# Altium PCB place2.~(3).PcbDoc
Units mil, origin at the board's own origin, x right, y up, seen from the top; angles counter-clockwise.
Board outline 2400 x 2000 mil, 2 copper layers (Top Layer, Bottom Layer), stack 62 mil thick; 51 components, 19 nets, 95 pads, 5 vias.
Unrouted connection lines stored in the file: 2.
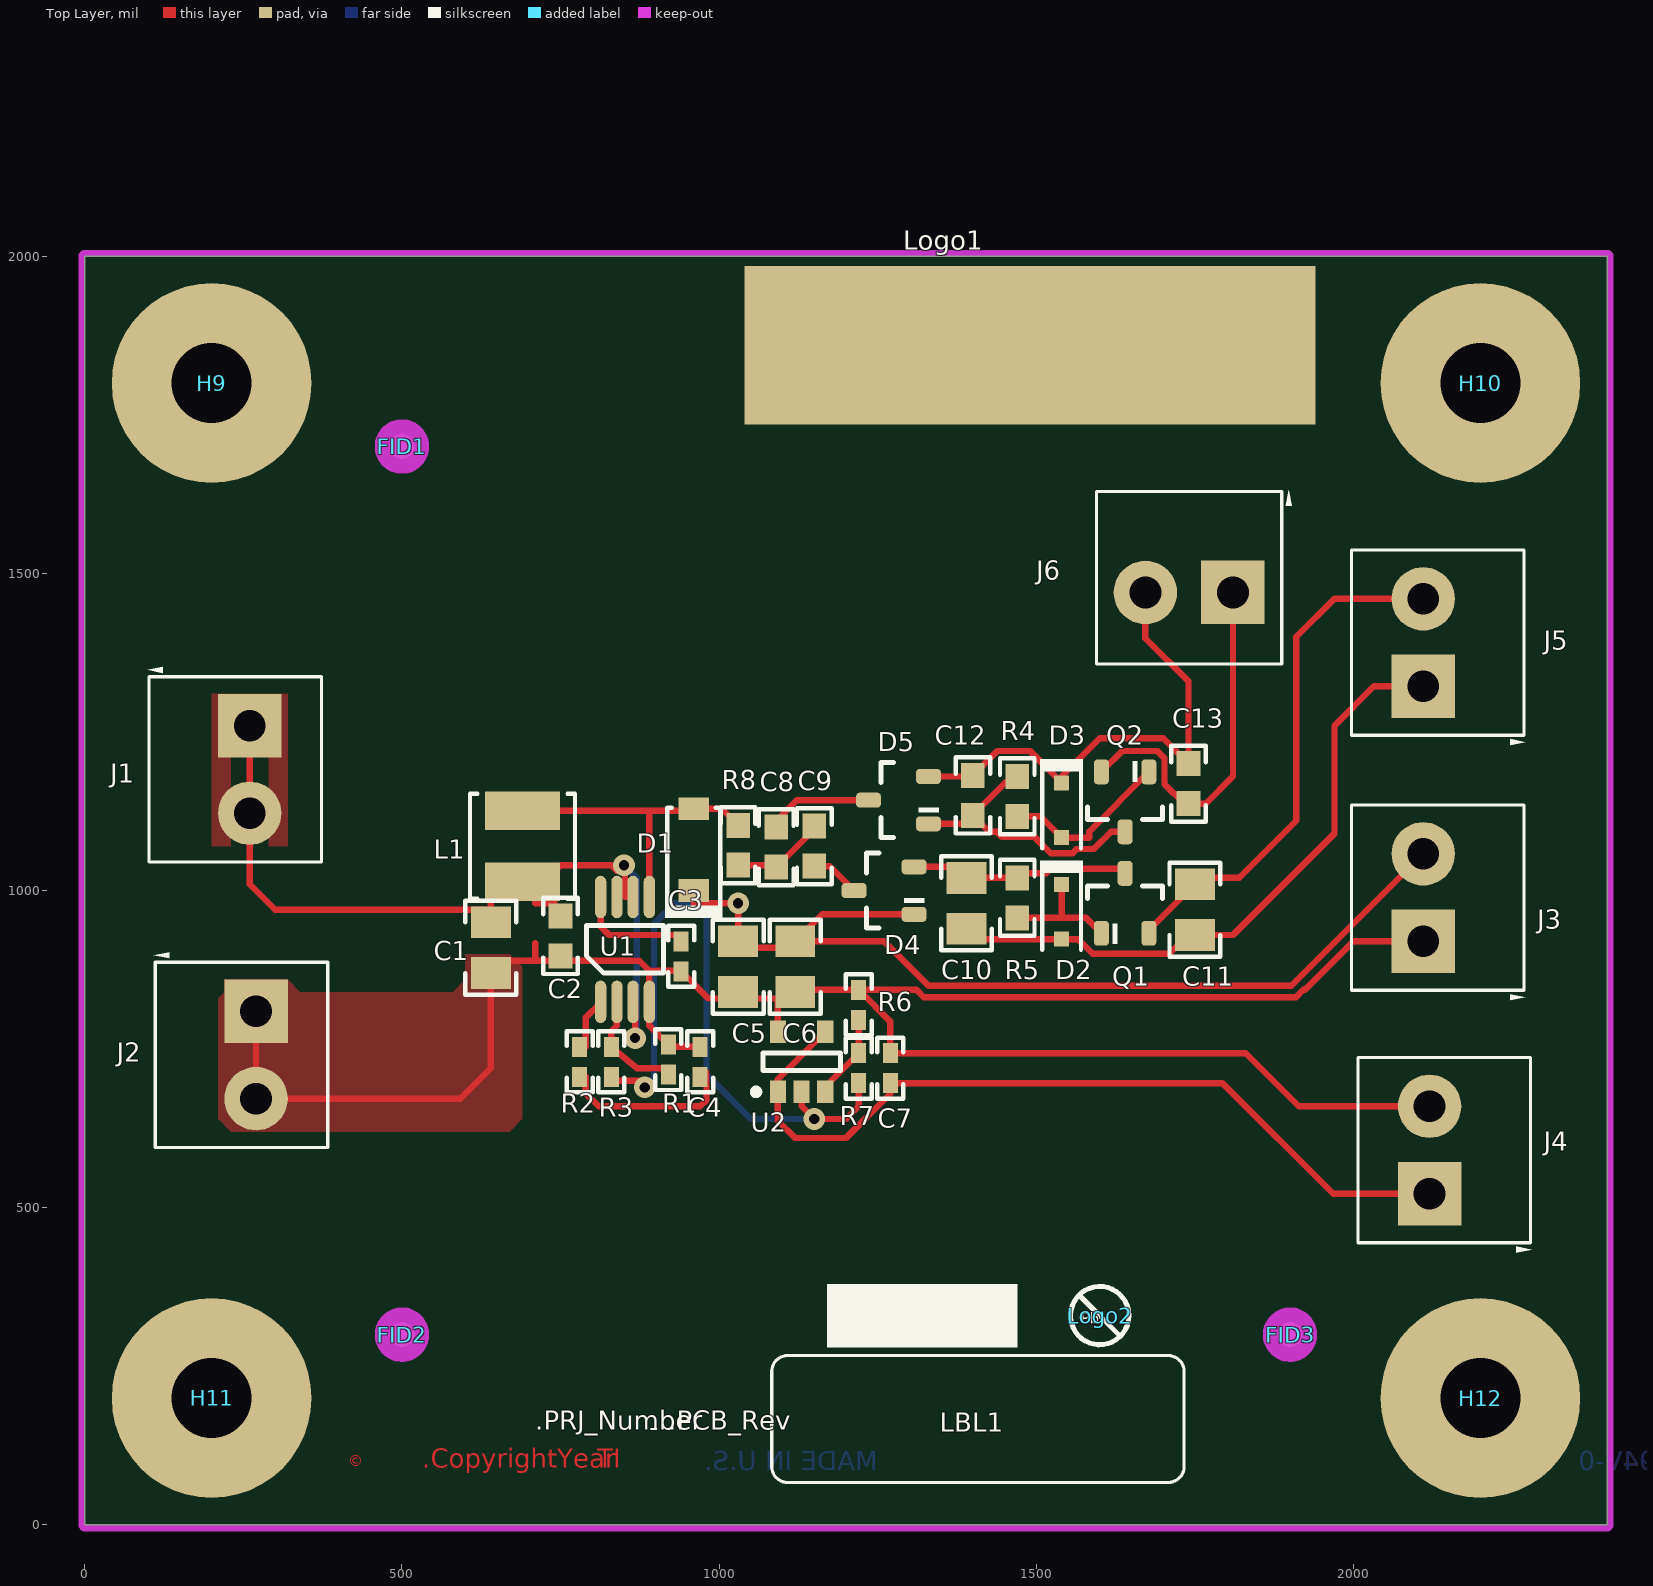
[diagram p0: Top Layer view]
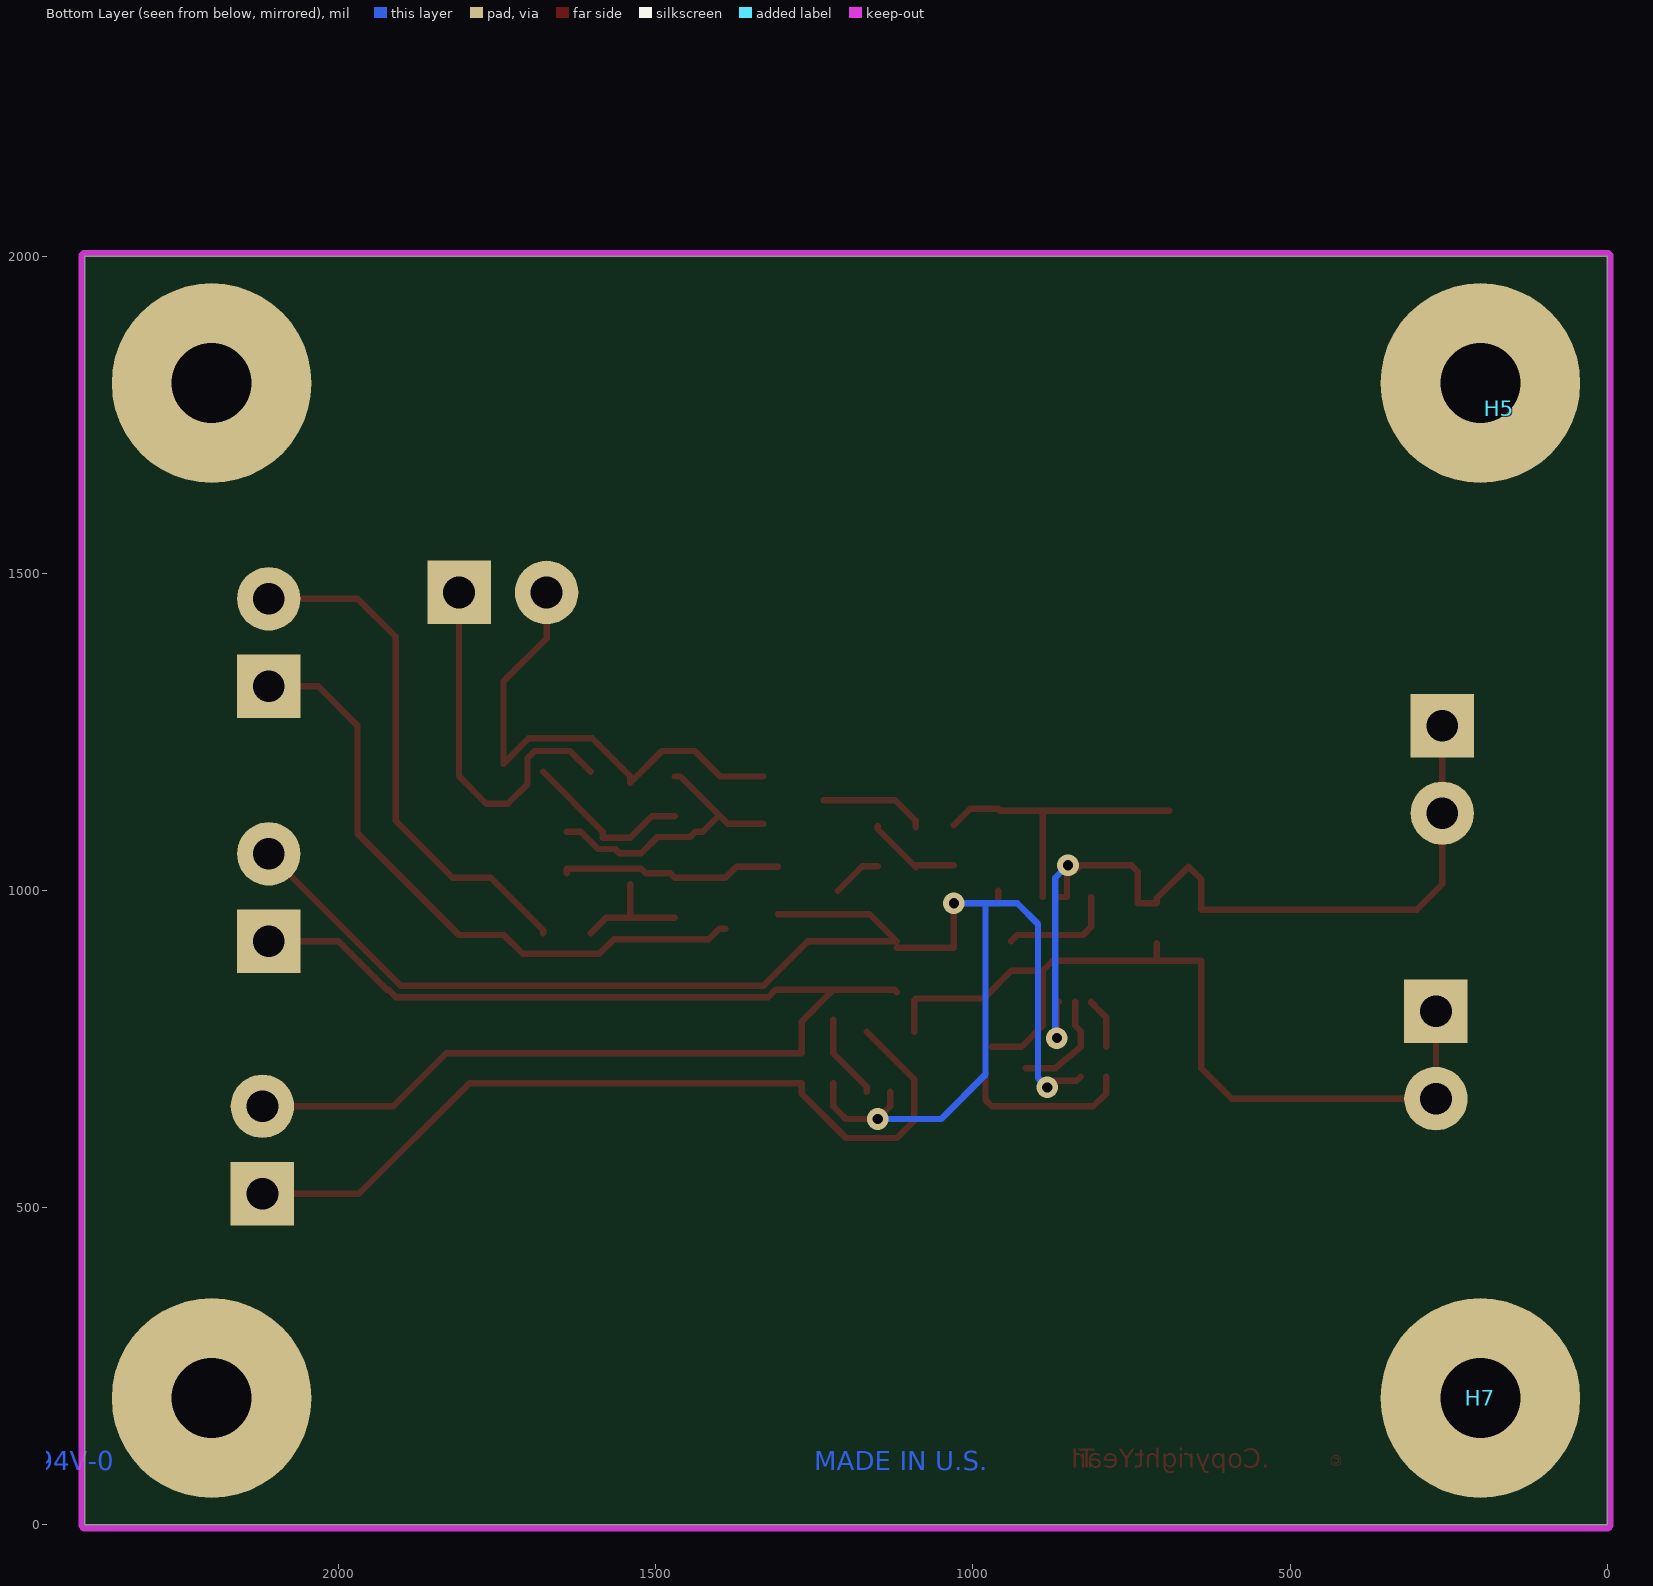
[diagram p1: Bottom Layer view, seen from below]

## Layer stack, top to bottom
Top Solder: solder mask 0.4, Solder Resist, Dk 3.5
Top Layer: signal copper 1.4
Dielectric1: core 59.2, FR-4, Dk 4.8
Bottom Layer: signal copper 1.4
Bottom Solder: solder mask 0.4, Solder Resist, Dk 3.5

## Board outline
0,0 2400,0 2400,2000 0,2000

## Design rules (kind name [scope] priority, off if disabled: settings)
AcuteAngle [All] p1: minimum=4.50000000000000E+0001 checktracksonly=FALSE
AssemblyTestPointUsage [All] p1: valid=2
Clearance Clearance_Keepouts [((IsTrack Or IsArc) And Not InPoly) And IsFree and IsKeepOut vs ((IsTrack Or IsArc) And Not InPoly) And IsFree and IsKeepOut] p1: gap=8
Clearance Clearance_BoardEdge_MountingHoles [OnCopper and InComponentClass('Mounting Holes') vs IsKeepOut] p2: gap=40
Clearance Clearance_BoardEdge_Poly [OnCopper and InPoly vs IsKeepOut] p3: gap=25
Clearance Clearance_BoardEdge [OnCopper and Not InComponentClass('Logo') and not InComponentClass('FiducialMark') and not InRegion(1000,500,4000,800) and Not IsKeepout vs IsKeepOut] p4: gap=75
Clearance Clearance_Poly [InPolygon] p5: gap=25
Clearance [All] p6: gap=7.87
ComponentClearance ComponentClearance_MountingHoles_FiducialMarks [InComponentClass('Mounting Holes') vs InComponentClass('FiducialMark')] p1: gap=10 collisioncheckmode=3 verticalgap=10 showdistances=FALSE
ComponentClearance ComponentClearance_Shunt [InComponentClass('Header') vs InComponentClass('Shunt')] p2: gap=0 collisioncheckmode=3 verticalgap=0 showdistances=FALSE
ComponentClearance ComponentClearance_Logo [InComponentClass('Logo')] p3: gap=10 collisioncheckmode=3 verticalgap=10 showdistances=FALSE
ComponentClearance ComponentClearance_ScrewToNut [(HasFootprint('NY PMS 440 0025 PH')) vs (HasFootprint('Keystone_1902C'))] p4: gap=5 collisioncheckmode=3 verticalgap=10 showdistances=FALSE
ComponentClearance ComponentClearance_MountingHoles [InComponentClass('Mounting Holes')] p5: gap=250 collisioncheckmode=3 verticalgap=100000 showdistances=FALSE
ComponentClearance ComponentClearance_SmallPassives [HasFootprint('0201*') or HasFootprint('0402*') or HasFootprint('0508') or HasFootprint('0603*') or HasFootprint('0612') or HasFootprint('0805*') or HasFootprint('0815*') or HasFootprint('0830*') or HasFootprint('1206*') or HasFootprint('1210*') or HasFootprint('1808*') or HasFootprint('1812*') or HasFootprint('1825*') or HasFootprint('2010*') or HasFootprint('2220*') or HasFootprint('2225*') or HasFootprint('2512*') or HasFootprint('2728*') or HasFootprint('3518*') vs HasFootprint('0201*') or HasFootprint('0402*') or HasFootprint('0508') or HasFootprint('0603*') or HasFootprint('0612') or HasFootprint('0805*') or HasFootprint('0815*') or HasFootprint('0830*') or HasFootprint('1206*') or HasFootprint('1210*') or HasFootprint('1808*') or HasFootprint('1812*') or HasFootprint('1825*') or HasFootprint('2010*') or HasFootprint('2220*') or HasFootprint('2225*') or HasFootprint('2512*') or HasFootprint('2728*') or HasFootprint('3518*')] p6: gap=20 collisioncheckmode=3 verticalgap=10 showdistances=FALSE
ComponentClearance ComponentClearance_THtoSMT [IsThruComponent vs IsSMTComponent] p7: gap=100 collisioncheckmode=3 verticalgap=30 showdistances=FALSE
ComponentClearance ComponentClearance_THtoTH [IsThruComponent vs IsThruComponent] p8: gap=118.11 collisioncheckmode=3 verticalgap=30 showdistances=FALSE
ComponentClearance [All] p9: gap=10 collisioncheckmode=3 verticalgap=10 showdistances=FALSE
DiffPairsRouting [All] p1: maxlimit=100 minlimit=10 mostfreqgap=10 toplayer_minwidth=15 toplayer_maxwidth=15 toplayer_prefwidth=15 bottomlayer_minwidth=15 bottomlayer_maxwidth=15 bottomlayer_prefwidth=15 maxuncoupledlength=1000
FabricationTestPointUsage TestPointUsage [All] p1: valid=2 allowmultiple=FALSE
FabricationTestpoint Testpoint [All] p1: side=3 testpointundercomponent=TRUE minsize=40 maxsize=100 preferedsize=60 minholesize=0 maxholesize=40 preferedholesize=32 testpointgrid=1 allowsidetop=TRUE allowsidebottom=TRUE usegrid=TRUE gridtolerance=0.01
FanoutControl Fanout_LCC [IsLCC] p1: bgadir=Out bgaviamode=Centered fanoutstyle=Auto fanoutdirection=Alternating viagrid=1 // Fanout_LCC (Default Rule)
FanoutControl Fanout_BGA [IsBGA] p2: bgadir=Out bgaviamode=Centered fanoutstyle=Auto fanoutdirection=Alternating viagrid=1 // Fanout_BGA (Default Rule)
FanoutControl Fanout_Default [All] p4: bgadir=Out bgaviamode=Centered fanoutstyle=Auto fanoutdirection=Alternating viagrid=1 // Fanout_Default (Default Rule)
FanoutControl Fanout_Small [(CompPinCount < 5)] p5: bgadir=Out bgaviamode=Centered fanoutstyle=Auto fanoutdirection=OutThenIn viagrid=1 // Fanout_Small (Default Rule)
HoleSize [All] p1: absolutevalues=TRUE maxlimit=251 minlimit=8 maxpercent=80.000 minpercent=20.000
MinimumAnnularRing MinimumAnnularRing_ThermalPadVias [IsVia and InAnyComponent] p1: minimumring=5.91
MinimumAnnularRing [All] p2: minimumring=9
MinimumSolderMaskSliver MinimumSolderMaskSliver_Logo [InComponentClass('Logo') vs InComponentClass('Logo')] p1: minsoldermaskwidth=0.7
MinimumSolderMaskSliver [All] p2: minsoldermaskwidth=3.94
PlaneConnect [All] p1: planeconnectstyle=Relief reliefexpansion=10 reliefentries=4 reliefconductorwidth=10 reliefairgap=10
PolygonConnect PolygonConnect_3 [All vs IsNamedPolygon('Top Layer-No Net 2')] p1: connectstyle=Direct reliefconductorwidth=10 reliefentries=4 polygonreliefangle="90 Angle" airgapwidth=10
PolygonConnect PolygonConnect_2 [All vs IsNamedPolygon('Top Layer-No Net 2')] p2: connectstyle=Direct reliefconductorwidth=10 reliefentries=4 polygonreliefangle="90 Angle" airgapwidth=10
PolygonConnect PolygonConnect_1 [All vs IsNamedPolygon('Top Layer-No Net 2')] p3: connectstyle=Direct reliefconductorwidth=10 reliefentries=4 polygonreliefangle="90 Angle" airgapwidth=10
PolygonConnect [All] p4: connectstyle=Direct reliefconductorwidth=10 reliefentries=4 polygonreliefangle="90 Angle" airgapwidth=10
RoutingVias ThermalPadVias [IsVia and InAnyComponent] p1: holewidth=7.87 width=19.68 viastyle="Through Hole" minholewidth=7.87 minwidth=19.68 maxholewidth=12.99 maxwidth=23.62
RoutingVias [All] p2: holewidth=16 width=34 viastyle="Through Hole" minholewidth=7.87 minwidth=26 maxholewidth=40 maxwidth=65
SilkToBoardRegionClearance [Not ((IsComment or IsDesignator) And (Hide <> 'False')) and not InRegion(1000,500,4000,800)] p1:
SilkToSilkClearance SilkToSilkClearance_Pb-FreeLogo [(HasFootprint('Pb-Free_Overlay_Medium') OR HasFootprint('Pb-Free_Overlay_Small')) vs (HasFootprint('Pb-Free_Overlay_Medium') OR HasFootprint('Pb-Free_Overlay_Small'))] p1: silktosilkclearance=0
SilkToSilkClearance [All] p2: silktosilkclearance=5
SilkToSolderMaskClearance "Silk to Solder Mask Opening" [All] p1: minsilkscreentomaskgap=1 clearancetoexposedcopper=FALSE
SolderMaskExpansion [All] p1: expansion=1.97
UnpouredPolygon [All] p1: allowunpoured=FALSE
Width [All] p1: maxlimit=100 minlimit=6 preferedwidth=10 checkconnectedcopper=TRUE
14 further rules are at their usual default settings.

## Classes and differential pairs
component class "TPS61085 reference board": C1 C2 C3 C4 C5 C6 C7 C8 C9 C10 C11 C12 C13 D1 D2 D3 D4 D5 J1 J2 J3 J4 J5 J6 L1 Q1 Q2 R1 R2 R3 R4 R5 R6 R7 R8 U1 U2
component class "Mounting Holes": H9 H10 H11 H12
component class Logo: Logo1
component class "TPS61085 reference board_Hardware": FID1 FID2 FID3 H5 H6 H7 H8 H9 H10 H11 H12 LBL1 Logo1 Logo2
component class FiducialMark: FID1 FID2 FID3
component class Label: LBL1

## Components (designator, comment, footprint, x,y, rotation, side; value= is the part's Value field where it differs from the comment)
C1 "GRM219R61A106KE44D" 0805_HV 640,910 r270 top
C2 "GRM185R61C105KE44D" 0603 750,928.5 r270 top
C3 "GRM155R71C104KA88D" 0402 940,896.38 r270 top
C4 "GRM155R61C222KA01D" 0402 970,730 r90 top
C5 "C2012X5R1E106K125AB" 0805_HV 1030,880 r270 top
C6 "C2012X5R1E106K125AB" 0805_HV 1120,880 r270 top
C7 "GRM155R71C104KA88D" 0402 1270,720 r90 top
C8 "06035C104KAT2A" 0603 1090,1068.5 r90 top
C9 "06035C104KAT2A" 0603 1150,1070 r90 top
C10 "C2012X7R1H105K125AB" 0805_HV 1390,980 r270 top
C11 "C2012X7R1H105K125AB" 0805_HV 1750,970 r270 top
C12 "GRM185R61C105KE44D" 0603 1400,1150 r90 top
C13 "GRM185R61C105KE44D" 0603 1740,1168.5 r90 top
D1 "MBR120LSFT1G" SOD-123FL 960,1064.47 r90 top
D2 "MMSZ5248BS-7-F" sod-323 1540,966.69 r270 top
D3 "MMSZ5236BS-7-F" sod-323 1540,1126.69 r270 top
D4 "BAT54SLT1G" SOT-23 1260,1000 r180 top
D5 "BAT54SLT1G" SOT-23 1282.76,1142.6 r180 top
FID1 "Fiducial" Fiducial10-20 500,1700 r0 top
FID2 "Fiducial" Fiducial10-20 500,300 r0 top
FID3 "Fiducial" Fiducial10-20 1900,300 r0 top
H5 "1902C" Keystone_1902C 170,1760 r180 bottom locked
H6 "1902C" Keystone_1902C 4750,3250 r180 bottom locked
H7 "1902C" Keystone_1902C 200,200 r180 bottom locked
H8 "1902C" Keystone_1902C 4050,200 r180 bottom locked
H9 "NY PMS 440 0025 PH" "NY PMS 440 0025 PH"#1 170,1760 r0 top
H10 "NY PMS 440 0025 PH" "NY PMS 440 0025 PH"#2 2900,2200 r0 top
H11 "NY PMS 440 0025 PH" "NY PMS 440 0025 PH"#3 200,200 r0 top locked
H12 "NY PMS 440 0025 PH" "NY PMS 440 0025 PH"#4 4050,200 r0 top
J1 "ED555/2DS" TERM_BLK_ED555-2DS 260,1260 r270 top
J2 "ED555/2DS" TERM_BLK_ED555-2DS 270,810 r270 top
J3 "ED555/2DS" TERM_BLK_ED555-2DS 2110,920 r90 top
J4 "ED555/2DS" TERM_BLK_ED555-2DS 2120,522 r90 top
J5 "ED555/2DS" TERM_BLK_ED555-2DS 2110,1322 r90 top
J6 "ED555/2DS" TERM_BLK_ED555-2DS 1810,1470 r180 top
L1 "LQH44PN3R3MP0L" IND_LQH44P 690,1070 r90 top
LBL1 "Size: 0.65\" x 0.20 \"" Label_650x200 1408,167 r0 top
Logo1 "Texas Instruments" TI_Stacked_SolderMask_Small 1490,1860 r180 top
Logo2 "Pb-Free Symbol" Pb-Free_Overlay_Small 1600,330 r0 top
Q1 "BC850CLT1G" SOT-23 1640,980 r90 top
Q2 "BC857C-7-F" SOT-23 1640,1140 r270 top
R1 "CRCW040216K0JNED" 0402 920,733.62 r270 top
R2 "CRCW040227K0JNED" 0402 780,730 r90 top
R3 "CRCW0402113KFKED" 0402 830,730 r270 top
R4 "CPF0603B2K0E" 0603 1470,1148.5 r90 top
R5 "CPF0603B2K0E" 0603 1470,988.5 r90 top
R6 "CRCW040227K0JNED" 0402 1220,820 r270 top
R7 "CRCW040227K0JNED" 0402 1220,720 r270 top
R8 "CRCW060310R0FKEA" 0603 1030,1071.5 r270 top
U1 "TPS61085DGKR" DGK0008A_N 851.61,907.32 r90 top
U2 "LM7321MF" MF05A_L 1130,730 r90 top

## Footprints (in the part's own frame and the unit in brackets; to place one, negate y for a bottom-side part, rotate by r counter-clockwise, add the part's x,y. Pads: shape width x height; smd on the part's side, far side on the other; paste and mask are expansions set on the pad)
0402 [mm] "0402 from SM-752 data"
  rect 0.8x0.6 smd: 1(-0.6,0) 2(0.6,0)
  silkscreen extent -1.22,-0.52 1.22,0.52, body extent -0.55,-0.3 0.55,0.3, height 0.6
0603 [mm] "0603 from SM-752 data"
  rect 1x0.95 smd: 1(-0.8,0) 2(0.8,0)
  silkscreen extent -1.52,-0.69 1.52,0.69, body extent -0.87,-0.47 0.87,0.47, height 0.85
0805_HV [mil] "0805 with 30mil clearance between pads"
  rect 50x63 smd: 1(-40,0) 2(40,0)
  silkscreen extent -74,-40 74,40, body extent -43,-29 43,29, height 43
DGK0008A_N [mm] "TSOP, 8-Leads, Body 3x3mm, Pitch 0.65mm, IPC Medium Density"
  oval 1.7x0.45 smd mask+0.05: 1(-2.1,0.975) 2(-2.1,0.325) 3(-2.1,-0.325) 4(-2.1,-0.975) 5(2.1,-0.975) 6(2.1,-0.325) 7(2.1,0.325) 8(2.1,0.975)
  silkscreen extent -0.95,-1.55 0.95,1.55, body extent -2.45,-1.5 2.45,1.5, height 0.94
Fiducial10-20 [mm]
  round 1 smd mask+0.5: 1(0,0)
  Top Layer keep-out circle w1.178: c0,0 r0.5
IND_LQH44P [mm] "Murata"
  rect 1.55x3 smd: 1(-1.425,0) 2(1.425,0)
  silkscreen extent -2.1,-2.1 2.1,2.1, body extent -2.1,-2.1 2.1,2.1, height 1.8
Keystone_1902C [mil] "Hex Standoff, 4-40 threaded, nylon"
  body extent -145,-126 146,126, height 501
Label_650x200 [mil] "Thermal Transfer Label"
  silkscreen extent -325,-100 325,100, body extent -326,-101 326,101, height 1
MF05A_L [mm] "SOT23, 5-Leads, Body 2.9x1.6mm, Pitch 0.95mm, Lead Span 2.8mm, IPC High Density"
  rect 0.9x0.65 smd: 1(-1.2,0.95) 2(-1.2,0) 3(-1.2,-0.95) 4(1.2,-0.95) 5(1.2,0.95)
  silkscreen extent -1.32,-1.55 0.35,1.95, body extent -0.9,-1.55 0.9,1.55, height 1.19
"NY PMS 440 0025 PH"#1 [mm] "4-40 nylon screw and mounting hole"
  round 8 hole 3.2: 1(0.762,1.016)
  body extent -3.3,-3.3 3.3,3.3, height 2.69
"NY PMS 440 0025 PH"#2 [mm] "4-40 nylon screw and mounting hole"
  round 8 hole 3.2: 1(-17.78,-10.16)
  body extent -3.3,-3.3 3.3,3.3, height 2.69
"NY PMS 440 0025 PH"#3 [mm] "4-40 nylon screw and mounting hole"
  round 8 hole 3.2: 1(0,0)
  body extent -3.3,-3.3 3.3,3.3, height 2.69
"NY PMS 440 0025 PH"#4 [mm] "4-40 nylon screw and mounting hole"
  round 8 hole 3.2: 1(-46.99,0)
  body extent -3.3,-3.3 3.3,3.3, height 2.69
Pb-Free_Overlay_Small [mil]
  silkscreen extent -46,-46 46,46
SOD-123FL [mm] "Copied from SOD-123"
  rect 0.915x1.22 smd: 1(-1.637,0) 2(1.637,0)
  silkscreen extent -2.74,-1.16 1.68,1.16, body extent -1.9,-0.9 1.9,0.9, height 1
sod-323 [mm] "NXP recommended land pattern"
  rect 0.6x0.6 smd paste-0.05: 1(-1.1,0) 2(1.1,0)
  silkscreen extent -2.06,-0.86 1.53,0.86, body extent -1.3,-0.67 1.3,0.68, height 1.1
SOT-23 [mm] "SOT23, 3-Leads, Body 2.9x1.3mm, Pitch 0.95mm, Lead Span 2.5mm, IPC Medium Density"
  rrect50% 1x0.6 smd: 1(-1.2,0.95) 2(-1.2,-0.95) 3(1.2,0)
  silkscreen extent -1.63,-1.5 0.7,1.5, body extent -1.16,-1.45 1.21,1.45, height 1
TERM_BLK_ED555-2DS [mil]
  rect 100x100 hole 50: 1(0,0)
  round 100 hole 50: 2(138,0)
  silkscreen extent -93,-161 215,113, body extent -69,-150 207,106, height 323
TI_Stacked_SolderMask_Small [mil]
  rect 900x250 smd paste-125 mask-125: 0(0,0)

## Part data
C1: "CAP, CERM, 10 μF, 10 V, +/- 10%, X5R, 0805"
C2 C12 C13: "CAP, CERM, 1 μF, 16 V, +/- 10%, X5R, 0603"
C3 C7: "CAP, CERM, 0.1 μF, 16 V, +/- 10%, X7R, 0402"
C4: "CAP, CERM, 2200 pF, 16 V, +/- 10%, X5R, 0402"
C5 C6: "CAP, CERM, 10 μF, 25 V, +/- 10%, X5R, 0805"
C8 C9: "CAP, CERM, 0.1 μF, 50 V, +/- 10%, X7R, 0603"
C10 C11: "CAP, CERM, 1 μF, 50 V, +/- 10%, X7R, 0805"
D1: "Diode, Schottky, 20 V, 1 A, SOD-123FL"
D2: "Diode, Zener, 18 V, 200 mW, SOD-323"
D3: "Diode, Zener, 7.5 V, 200 mW, SOD-323"
D4 D5: "Diode, Schottky, 30 V, 0.2 A, SOT-23"
FID1 FID2 FID3: "Fiducial mark.  There is nothing to buy or mount."
H5 H6 H7 H8: "Standoff, Hex, 0.5\"L #4-40 Nylon"
H9 H10 H11 H12: "Machine Screw, Round, #4-40 x 1/4, Nylon, Philips panhead"
J1 J2 J3 J4 J5 J6: "Terminal Block, 6A, 3.5mm Pitch, 2-Pos, TH"
L1: "Inductor, Shielded Drum Core, Ferrite, 3.3 μH, 1.77 A, 0.065 ohm, SMD"
LBL1: library part THT-14-423-10, "Thermal Transfer Printable Labels, 0.650\" W x 0.200\" H - 10,000 per roll"
Logo1: library part TI_Logo, "Texas Instrument Corporate Signature"
Logo2: library part Pb-Free
Q1: library part "BC850CLT1G, ON Semiconductor", "Transistor, NPN, 45 V, 0.1 A, SOT-23"
Q2: library part "BC857C-7-F, Diodes Inc.", "Transistor, PNP, 45 V, 0.1 A, SOT-23"
R1: "RES, 16 k, 5%, 0.063 W, 0402"
R2 R6 R7: "RES, 27 k, 5%, 0.063 W, 0402"
R3: "RES, 113 k, 1%, 0.063 W, 0402"
R4 R5: "RES, 2.00 k, 0.1%, 0.063 W, 0603"
R8: "RES, 10.0, 1%, 0.1 W, 0603"
U1: "18.5 V, 2 A, 650 KHz / 1.2 MHz Step-Up DC-DC Converter with Forced PWM Mode, 2.3 to 6 V, -40 to 85 degC, 8-pin SOP (DGK8), Green (RoHS & no Sb/Br)"
U2: "Single 30V High Output Current and Unlimited Capacitive Load Op Amp"

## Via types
v1: diameter 34, hole 16, Top Layer to Bottom Layer, 4 vias
v2: diameter 34/34 (per signal layer), hole 16, Top Layer to Bottom Layer, 1 vias

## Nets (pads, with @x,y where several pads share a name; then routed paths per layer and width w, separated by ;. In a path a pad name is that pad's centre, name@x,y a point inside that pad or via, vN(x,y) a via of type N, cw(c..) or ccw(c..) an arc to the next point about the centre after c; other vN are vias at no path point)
NetC3_1: C3.1 U1.8 | length 183.2
  Top Layer w10: U1.8 813.23,943.23 826.46,930 930,930 C3.1
NetC4_1: C4.1 R2.1 | length 271.6
  Top Layer w10: R2.1@790,706.38 790,680 810,660 970,660 980,670 C4.1@980,712.76
NetC8_1: C8.1 C9.2 R8.2 | length 147.8
  Top Layer w10: R8.2 C8.1@1088.5,1040 ; C8.1 1150,1097.01 C9.2
NetC8_2: C8.2 D5.3 | length 169
  Top Layer w10: C8.2 1090,1110 1122.6,1142.6 D5.3
NetC9_1: C9.1 D4.3 | length 78.7
  Top Layer w10: C9.1 1174.25,1038.5 D4.3
NetC10_1: C10.1 D4.2 Q1.3 R5.2 | length 353.5
  Top Layer w10: D4.2 1372.6,1037.4 C10.1 R5.2 1477.24,1027.24 1515.42,1027.24 1522.86,1034.68 1640,1034.68 Q1.3
NetC12_1: C12.1 D5.1 Q2.3 R4.2 | length 449.9
  Top Layer w10: D5.1 1386.69,1105.2 C12.1 ; R4.2 1461.5,1180 C12.1 ; Q2.3 1617.88,1092.76 1590.63,1065.51 1563.95,1065.51 1557.14,1058.7 1522.86,1058.7 1497.11,1084.45 1445.97,1084.45 1437.66,1092.76 1425.75,1092.76 C12.1
NetD2_1: D2.1 Q1.1 R5.1 | length 195.6
  Top Layer w10: R5.1 1540,957.01 ; D2.1 1540,957.01 ; Q1.1 1578.35,957.01 1540,957.01
NetD3_2: D3.2 Q2.1 R4.1 | length 270
  Top Layer w10: R4.1 1506.38,1117.01 D3.2 1583.23,1083.39 1583.23,1093.07 Q2.1
NetR1_2: R1.2 R3.1 U1.2 | length 173.3
  Top Layer w10: U1.2 838.82,786.82 830,778 R3.1 870,720 R1.2@916.38,720
NetR2_2: R2.2 U1.1 | length 87.2
  Top Layer w10: R2.2@790,753.62 790,800 813.23,823.23 U1.1 U1.1@808.58,820
NetR6_2: R6.2 R7.1 U2.3 | length 135.4
  Top Layer w10: U2.3 1167.4,691.02 R7.1 R6.2
PGND: C1.2 C2.2 C3.2 C4.2 C5.2 C6.2 C7.2 C10.2 C11.2 C12.2 C13.2 D2.2 D3.1 D5.2 J2.1 J2.2 J3.1 J4.2 J5.1 J6.2 R1.1 R6.1 U1.4 U2.5 | length 5319.8
  Top Layer w10: J2.1 J2.2 592,672 640,720 640,889.62 708.9,889.62 ; 710,917.01 710,890.72 708.9,889.62 ; C4.2 923.62,753.62 R1.1 890,787.24 U1.4 890,873.62 ; U2.5 1092.6,827.4 1090,830 982.76,830 C3.2 939.13,873.62 890,873.62 ; C6.2 1123.62,843.62 R6.1 ; D5.2 1398.5,1180 C12.2 1438.5,1220 1490,1220 D3.1 1540,1180 1600,1240 1700,1240 C13.2 1740,1330 1672,1398 J6.2 ; C10.2 1400,940 1416.61,923.39 D2.2 1565.73,923.39 1588.91,900.2 1709.8,900.2 1739.61,930 C11.2 1810,930 1970,1090 1970,1260 2032,1322 J5.1 ; J3.1 2000,920 1923.62,843.62 1920.9,843.62 1909.4,832.13 1322.6,832.13 1311.1,843.62 R6.1 ; J4.2@2160,660 1913.62,660 1830,743.62 C7.2 1270,793.62 R6.1 ; 708.9,889.62 874,889.62 890,873.62
SW: D1.2 L1.2 R8.1 U1.5 | length 488
  Top Layer w10: L1.2 890,1126.1 ; U1.5 890,1126.1 ; R8.1 1004.06,1128.94 D1.2 957.17,1126.1 890,1126.1
VCOM: C7.1 J4.1 U2.1 U2.4 | length 1367.2
  Top Layer w10: U2.4 1092.6,702.44 U2.1 1092.6,637.4 1120,610 1200,610 1270,680 C7.1 1793.62,696.38 1968,522 J4.1@2160,522
VGH: C11.1 J5.2 Q1.2 | length 823.6
  Top Layer w10: Q1.2 1677.4,937.4 C11.1 1760,1020 1820,1020 1910,1110 1910,1400 1970,1460 J5.2
VGL: C13.1 J6.1 Q2.2 | length 587.1
  Top Layer w10: Q2.2 1635.35,1220 1690,1220 1690.2,1219.8 1691.09,1219.8 1702.09,1208.8 1702.09,1167.91 1732.99,1137.01 C13.1 1767.01,1137.01 1810,1180 J6.1
VIN: C1.1 C2.1 J1.1 J1.2 L1.1 U1.3 U1.6 U1.7 | length 1392
  Top Layer w10: J1.1 J1.2 260,1010 300.38,969.62 640,969.62 640,1017.8 660,1037.8 710,987.8 710,980 740,980 740,1030 750,1040 830,1040 v1@838.82,1031.18 ; v1(850,1040) 851.61,1038.39 851.61,990 U1.6 ; U1.3 867.5,821.56 v1(867.5,767.5)
  Bottom Layer w10: v1(850,1040) 870,1020 870,770 v1(867.5,767.5)
VO: C5.1 C6.1 D1.1 D4.1 J3.2 R3.2 R7.2 U2.2 | length 2674
  Top Layer w10: R3.2 836.3,700.08 872.5,700.08 v1(882.71,689.87) ; D1.1 960,980 v1(1030,980) C5.1 1030,910 C6.1@1120,910 ; U2.2 1130,660 v2(1150,640) ; v2@1150,650 v2(1150,640) ; R7.2 1220,660 1210,650 1200,640 v2(1150,640) ; D4.1 1162.6,962.6 C6.1 1260,920 1330,850 1902,850 J3.2
  Bottom Layer w10: v1(882.71,689.87) 897.37,704.54 897.37,947.37 930,980 980,980 ; v1(1030,980) 980,980 ; v2(1150,640) 1050,640 980,710 980,980
pads on no net: FID1.1 FID2.1 FID3.1 H9.1 H10.1 H11.1 H12.1 Logo1.0

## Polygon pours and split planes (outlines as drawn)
VIN on Top Layer "Top Layer-No Net 2" (solid, pour order 26): 200,1310 320,1310 320,1070 200,1070 200,1310
VIN on Top Layer "Top Layer-No Net" (solid, shelved, pour order 13): 300,-90 300,-440 310,-450 300,-460
PGND on Top Layer "Top Layer-No Net 1" (solid, pour order 11): 220,860 320,860 340,840 580,840 600,860 600,870 600,890 600,900 670,900 690,880 690,640 670,620 230,620 210,640 210,660 210,830 220,840 220,860

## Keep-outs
Keep-Out Layer:
  lines w10: -5,0 ccw(c0,0) 0,-5 ; -5,0 ccw(c0,0) 0,-5 ; -5,0 -5,2000 ; -5,2000 cw(c0,2000) 0,2005 ; -5,2000 cw(c0,2000) 0,2005 ; 0,-5 2400,-5 ; 0,2005 2400,2005 ; 2400,-5 ccw(c2400,0) 2405,0 ; 2400,-5 ccw(c2400,0) 2405,0 ; 2400,2005 cw(c2400,2000) 2405,2000 ; 2400,2005 cw(c2400,2000) 2405,2000 ; 2405,0 2405,2000
  text ".Layer_Name" at 577,-858.49 h30

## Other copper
Top Layer:
  text ".CopyrightYear" at 532,90 h30
  text "TI" at 808,90 h30
  text "©" at 415,86.48 h30
  text ".Layer_Name" at 577,-858.49 h30
Bottom Layer:
  text ".VersionControl_RevNumber" at 3891,179.5 h30
  text "SVN:" at 4130,180 h30
  text "MADE IN U.S." at 1250,86.5 h30
  text "UL94V-0" at 2529.5,86.5 h30
  text ".Layer_Name" at 577,-858.49 h30

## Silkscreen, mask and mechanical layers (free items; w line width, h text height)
Top Overlay:
  region: 1470,380 1170,380 1170,280 1470,280
  text ".PRJ_Number" at 710,150 h30
  text ".PCB_Rev" at 920,150 h30
  text "-" at 890,140 h30
  text ".Layer_Name" at 577,-858.49 h30
Bottom Overlay:
  text ".Layer_Name" at 577,-858.49 h30
Top Paste:
  text ".Layer_Name" at 577,-858.49 h30
Bottom Paste:
  text ".Layer_Name" at 577,-858.49 h30
Top Solder:
  text ".Layer_Name" at 577,-858.49 h30
  text ".Layer_Name" at 577,-858.49 h30
Bottom Solder:
  text ".Layer_Name" at 577,-858.49 h30
Drill Guide:
  text ".Layer_Name" at 577,-858.49 h30
M1 Board Outline:
  lines w10: 690,-1530 700,-1530 ; 0,0 2400,0 2400,2000 0,2000 0,0
  text ".Layer_Name" at 577,-858.49 h30
M2 Board Dimensions:
  rectangle: 0,-275 125,-150
  rectangle: 125,-400 500,-275
  lines w7: 0,-275 1000,-275 ; 125,-400 125,-150 ; 250,-400 250,-150 ; 500,-400 500,-150 ; 750,-400 750,-150 ; 0,-400 1000,-400 1000,-150 0,-150 0,-400
  text ".Layer_Name" at 577,-858.49 h30
M3 3D STEP Top:
  text ".Layer_Name" at 577,-858.49 h30
M4 3D STEP Bottom:
  text ".Layer_Name" at 577,-858.49 h30
M5 Assembly Top:
  lines w10: -292,-930.17 6308,-930.17 ; -292,-726.83 6310,-726.83 ; -292,-523.5 -292,-1133.5 3713,-1133.5 6310,-1133.5 6310,-523.5 -291.5,-523.5 -291.5,-1133.5 1284,-1133.5 ; 2173,-1133.5 2173,-523.5 ; 3440,-726.83 3440,-523.5 ; 4280,-726.83 4280,-523.5 ; 4902,-1140 4902,-937.17
  text "COMPONENTS MARKED 'DNP' SHOULD NOT BE POPULATED." at 1153.5,-318.5 h30
  text "ASSEMBLY VARIANT:" at 1153,-434 h30
  text ".VariantName" at 2189,-434 h30
  text "PCB VIEWED FROM TOP SIDE" at -228.5,-655.67 h30
  text "BOARD #:" at 2248,-655.67 h30
  text ".PRJ_Number" at 2793.5,-655.67 h30
  text "REV:" at 3638,-655.67 h30
  text ".PCB_Rev" at 3929.5,-655.67 h30
  text "SVN REV:" at 4476,-655.67 h30
  text ".VersionControl_RevNumber" at 4982,-655.67 h30
  text "PLOT NAME =" at -228.5,-1064.34 h30
  text ".plot_File_Name" at 577,-1064.34 h30
  text "GENERATED    :" at 2250,-1064.34 h30
  text ".Print_Date" at 3119.5,-1064.34 h30
  text ".Print_Time" at 3848.5,-1064.34 h30
  text "TEXAS INSTRUMENTS" at 5113,-1064.34 h30
M6 Assembly Bottom:
  lines w10: -292.5,-727.33 6309.5,-727.33 ; -290.5,-930.67 6309.5,-930.67 ; 1115.5,-1140.5 1115.5,-937.67 ; 1737.5,-727.33 1737.5,-524 ; 2577.5,-727.33 2577.5,-524 ; 3844.5,-1134 3844.5,-524 ; 4733.5,-1134 6309,-1134 6309,-524 -292.5,-524 -292.5,-1134 2304.5,-1134 6309.5,-1134 6309.5,-524
  text "COMPONENTS MARKED 'DNP' SHOULD NOT BE POPULATED." at 6102,-318 h30
  text ".VariantName" at 5058,-434 h30
  text "ASSEMBLY VARIANT:" at 6097,-434 h30
  text ".VersionControl_RevNumber" at 1035.5,-656.17 h30
  text "SVN REV:" at 1541.5,-656.17 h30
  text ".PCB_Rev" at 2088,-656.17 h30
  text "REV:" at 2379.5,-656.17 h30
  text ".PRJ_Number" at 3224,-656.17 h30
  text "BOARD #:" at 3769.5,-656.17 h30
  text "PCB VIEWED FROM BOTTOM SIDE" at 6246,-656.17 h30
  text "TEXAS INSTRUMENTS" at 904.5,-1064.84 h30
  text ".Print_Time" at 2169,-1064.84 h30
  text ".Print_Date" at 2898,-1064.84 h30
  text "GENERATED    :" at 3767.5,-1064.84 h30
  text ".plot_File_Name" at 5440.5,-1064.84 h30
  text "PLOT NAME =" at 6246,-1064.84 h30
M9 Title Sheet:
  drawing of 57 lines, arcs and shapes, not listed
  text "1" at 739.84,8036.5 h30
  text "2" at 3235.5,8036.5 h30
  text "3" at 5724.84,8036.5 h30
  text "4" at 8231.51,8036.5 h30
  text "5" at 10730.5,8036.5 h30
  text "6" at 13235.5,8036.5 h30
  text "A" at -416.5,6893.5 h30
  text "A" at 14383.5,6893.5 h30
  text "B" at -416.5,4513.5 h30
  text "B" at 14383.5,4513.5 h30
  text "C" at -416.5,2138.5 h30
  text "C" at 14383.5,2138.5 h30
  text "PROJECT TITLE:" at 11343.5,277.5 h30
  text ".PRJ_Title" at 11393.5,144.17 h30
  text "DESIGNED FOR:" at 11343.5,-23.5 h30
  text ".PRJ_Customer" at 11393.5,-163.5 h30
  text "D" at -416.5,-231.5 h30
  text "D" at 14383.5,-231.5 h30
  text "FILE NAME:" at 11343.5,-323.5 h30
  text ".PCB_File_Name_No_Path" at 11393.5,-443.5 h30
  text "Texas Instruments (TI) and/or its licensors do not warrant the accuracy or completeness of this specification" at 6374,-605.34 h30
  text "ENGINEER:" at 11343.5,-613.5 h30
  text "LAYOUT BY:" at 12848.5,-613.5 h30
  text "or any information contained therein. TI and/or its licensors do not warrant that this design will meet" at 6329.01,-718 h30
  text ".PRJ_Engineer" at 11393.5,-768.49 h30
  text ".PCB_Layout" at 12899,-768.49 h30
  text "the specifications, will be suitable for your application or fit for any particular purpose, or will operate in" at 6329.01,-830.67 h30
  text ".Layer_Name" at 577,-858.49 h30
  text "ALTIUM DESIGNER VERSION:" at 12848.5,-923.5 h30
  text "an implementation. TI and/or its licensors do not warrant that the design is production worthy. You should" at 6329.01,-943.33 h30
  text "completely validate and test your design implementation to confirm the system functionality for your application." at 6374,-1056 h30
  text ".print_Scale" at 11393.5,-1056.83 h30
  text ".Application_BuildNumber" at 12899,-1056.83 h30
  text "1" at 739.84,-1263.5 h30
  text "2" at 3235.5,-1263.5 h30
  text "3" at 5724.84,-1263.5 h30
  text "4" at 8231.51,-1263.5 h30
  text "5" at 10730.5,-1263.5 h30
  text "6" at 13235.5,-1263.5 h30
M10 Fab Notes:
  drawing of 185 lines, arcs and shapes, not listed
  text "DESIGN INFORMATION" at 12381.02,5910 h30
  text "MIN. TRACK WIDTH:" at 11736.46,5730 h30
  text "8" at 12832.7,5730 h30
  text "MIL" at 12987.46,5730 h30
  text "MIN. CLEARANCE:" at 11736.46,5598 h30
  text "0.2" at 12772.7,5598 h30
  text "mm" at 12987.46,5598 h30
  text "MIN. VIA PAD SIZE:" at 11736.46,5466 h30
  text "24" at 12802.71,5466 h30
  text "MIL" at 12987.46,5466 h30
  text "0.05mm (2MIL)" at 12431.46,5324.29 h30
  text "MINIMUM ANNULAR RING" at 11407.23,5320 h30
  text "EXTERNAL" at 13139.46,5320 h30
  text "PER" at 11607.23,5202 h30
  text "IPC-D-275 CLASS 2 LEVEL C" at 11827.23,5202 h30
  text "MIL, HOLES" at 13315.46,5089.71 h30
  text "+/-" at 12923,5089 h30
  text "+/-" at 13777,5089 h30
  text "REGISTRATION TOLERANCES:" at 11407.23,5084 h30
  text "METAL" at 12607,5084 h30
  text "5" at 13183.2,5084 h30
  text "3" at 14016.2,5084 h30
  text "MIL" at 14132.46,5084 h30
  text "MATERIAL:" at 11332.46,4874.54 h30
  text "FR-4 High Tg" at 12318.9,4734.21 h30
  text "FR-408" at 11753.46,4725.64 h30
  text "X" at 12165.46,4725.64 h30
  text "OTHER" at 13241.46,4725.64 h30
  text "62 MIL (1.6mm) +/-10%" at 12073.56,4562.92 h30
  text "THICKNESS:" at 11407.23,4558.64 h30
  text "X" at 11945.4,4558.64 h30
  text "OTHER" at 13358.46,4558.64 h30
  text "TOLERANCE:" at 11407.23,4400.64 h30
  text "X" at 12246.53,4400.64 h30
  text "ANSI IPC-6012 TYPE 3 CLASS 2" at 12433.48,4400.64 h30
  text "OTHER +/-" at 12433.46,4244.64 h30
  text "BOW & TWIST:" at 11407.23,4087.64 h30
  text "X" at 12246.53,4087.64 h30
  text "ANSI IPC-6012 TYPE 3 CLASS 2" at 12433.48,4087.64 h30
  text "OTHER +/-" at 12433.46,3929.13 h30
  text "DRILLING:" at 11332.46,3790.64 h30
  text "REFERENCE:" at 11407.23,3673.64 h30
  text "X" at 12055.46,3673.64 h30
  text "AS SHOWN" at 12242.46,3673.64 h30
  text "X" at 12956.46,3673.64 h30
  text "NC_DRILL FILES" at 13093.46,3673.64 h30
  text "PTH MIN COPPER THICKNESS:" at 11407.23,3515.64 h30
  text "X" at 12757.46,3515.64 h30
  text "1MIL" at 12894.46,3515.64 h30
  text "OTHER" at 13391.46,3515.64 h30
  text "BOARD FINISH:" at 11332.46,3356.64 h30
  text "SILKSCREEN:" at 11487.68,3238.64 h30
  text "X" at 12436.46,3238.64 h30
  text "TOP" at 12562.46,3238.64 h30
  text "X" at 12946.46,3238.64 h30
  text "BOTTOM" at 13073.46,3238.64 h30
  text "SILKSCREEN COLOR:" at 11487.68,3071.64 h30
  text "X" at 12435.42,3071.64 h30
  text "WHITE" at 12562.46,3071.64 h30
  text "OTHER" at 13073.46,3071.64 h30
  text "SOLDER RESIST COLOR:" at 11487.68,2901.64 h30
  text "X" at 12055.42,2742.44 h30
  text "GREEN" at 12182.46,2742.44 h30
  text "BLUE" at 12773.46,2742.44 h30
  text "OTHER" at 13311.46,2742.44 h30
  text "IMMERSION GOLD (ENIG)" at 12393.46,2553.92 h30
  text "ENEPIG" at 13731,2550.64 h30
  text "SURFACE FINISH:" at 11332.46,2549.64 h30
  text "X" at 12206.51,2549.64 h30
  text "IMM. TIN/SILVER OR EQUIV" at 11662,2392.64 h30
  text "OTHER" at 13093.46,2392.64 h30
  text "ARRAY/PANEL:" at 11332.46,2213.64 h30
  text "CUT AND TRIM PER MECH LAYER 1" at 12393.46,2209.35 h30
  text "N.C. ROUTE" at 12393.46,2057.64 h30
  text "X" at 13072.46,2057.64 h30
  text "V. SCORE" at 13259.46,2057.64 h30
  text "CERTIFICATION:" at 11332.46,1920.64 h30
  text "MATERIALS AND WORKMANSHIP FOR ALL PCBS" at 12057.46,1920.64 h30
  text "TO MEET OR EXCEED THE REQUIREMENTS OF:" at 12057.46,1822.64 h30
  text "X" at 11683.96,1686.13 h30
  text "ANSI IPC-A-600F CLASS ->" at 11822.96,1686.13 h30
  text "X" at 13462.02,1686.13 h30
  text "2" at 13580.96,1686.14 h30
  text "1" at 13265.96,1684.64 h30
  text "3" at 13934.96,1684.64 h30
  text "X" at 11686.02,1526.64 h30
  text "UL 94V-0" at 11822.96,1526.64 h30
  text "X" at 12498.02,1526.64 h30
  text "RoHS" at 12634.96,1526.64 h30
  text "OTHER" at 13279.36,1526.64 h30
  text "PER ORDER" at 13676.42,1526.64 h30
  text "ADDITIONAL REQUIREMENTS:" at 11332.46,1385.64 h30
  text "MICROSECTION:" at 11407.23,1270.64 h30
  text "YES" at 12312.96,1270.64 h30
  text "REQUIRED" at 13174.46,1114.49 h30
  text "BARE BOARD ELEC. TEST:" at 11407.23,1111.64 h30
  text "NONE" at 12712.96,1111.64 h30
  text "X" at 13047.46,1111.64 h30
  text "PER ORDER" at 13766.46,1111.64 h30
  text "MANUFACTURER'S UL:" at 11407.23,954.64 h30
  text "RAIL" at 12572.96,950.35 h30
  text "METAL" at 13064.77,950.35 h30
  text "X" at 13440,950 h30
  text "SILK" at 13576.46,950.35 h30
  text ".Layer_Name" at 577,-858.49 h30
M11 Gerber Information:
  lines w10: -292,-930.17 6308,-930.17 ; -292,-726.83 6310,-726.83 ; -292,-523.5 -292,-1133.5 3713,-1133.5 6310,-1133.5 6310,-523.5 -291.5,-523.5 -291.5,-1133.5 1284,-1133.5 ; 2173,-1133.5 2173,-523.5 ; 3440,-726.83 3440,-523.5 ; 4280,-726.83 4280,-523.5 ; 4902,-1140 4902,-937.17
  text "ALL ARTWORK VIEWED FROM TOP SIDE" at -228.5,-655.67 h30
  text "BOARD #:" at 2248,-655.67 h30
  text ".PRJ_Number" at 2793.5,-655.67 h30
  text "REV:" at 3638,-655.67 h30
  text ".PCB_Rev" at 3929.5,-655.67 h30
  text "SVN REV:" at 4476,-655.67 h30
  text ".VersionControl_RevNumber" at 4982,-655.67 h30
  text "LAYER NAME =" at -228.5,-858.49 h30
  text "PLOT NAME =" at -228.5,-1064.34 h30
  text ".plot_File_Name" at 577,-1064.34 h30
  text "GENERATED    :" at 2250,-1064.34 h30
  text ".Print_Date" at 3119.5,-1064.34 h30
  text ".Print_Time" at 3848.5,-1064.34 h30
  text "TEXAS INSTRUMENTS" at 5113,-1064.34 h30
M12 Stackup:
  drawing of 191 lines, arcs and shapes, not listed
  text "Layer" at 9760.34,7380 h30
  text "Name" at 9965.3,7380 h30
  text "Material" at 10430.17,7380 h30
  text "Thickness" at 10860.06,7380 h30
  text "Constant" at 11184.97,7380 h30
  text "Board Layer Stack" at 11469.9,7380 h30
  text "1" at 9760.34,7320 h30
  text "Top Overlay" at 9965.3,7320 h30
  text "2" at 9760.34,7260 h30
  text "Top Solder" at 9965.3,7260 h30
  text "Solder Resist" at 10430.17,7260 h30
  text "0.40mil" at 10860.06,7260 h30
  text "3.5" at 11184.97,7260 h30
  text "3" at 9760.34,7200 h30
  text "Top Layer" at 9965.3,7200 h30
  text "Copper" at 10430.17,7200 h30
  text "1.40mil" at 10860.06,7200 h30
  text "4" at 9760.34,7140 h30
  text "Dielectric1" at 9965.3,7140 h30
  text "FR-4" at 10430.17,7140 h30
  text "59.20mil" at 10860.06,7140 h30
  text "4.8" at 11184.97,7140 h30
  text "5" at 9760.34,7080 h30
  text "Bottom Layer" at 9965.3,7080 h30
  text "Copper" at 10430.17,7080 h30
  text "1.40mil" at 10860.06,7080 h30
  text "6" at 9760.34,7020 h30
  text "Bottom Solder" at 9965.3,7020 h30
  text "Solder Resist" at 10430.17,7020 h30
  text "0.40mil" at 10860.06,7020 h30
  text "3.5" at 11184.97,7020 h30
  text "7" at 9760.34,6960 h30
  text "Bottom Overlay" at 9965.3,6960 h30
  text ".Layer_Name" at 577,-858.49 h30
M13 Component Bodies Top:
  text ".Layer_Name" at 577,-858.49 h30
M14 Component Bodies Bottom:
  text ".Layer_Name" at 577,-858.49 h30
M15 Courtyards Top:
  text ".Layer_Name" at 577,-858.49 h30
M16 Courtyards Bottom:
  text ".Layer_Name" at 577,-858.49 h30
Drill Drawing:
  circle w1: c5653.79,3229.48 r14.51
  lines w1: 5639.28,3127.92 5668.3,3127.92 5668.3,3156.94 5639.28,3156.94 5639.28,3127.92 ; 5639.28,3331.03 5668.3,3331.03 5653.79,3302.02 5639.28,3331.03
  lines w12: 5600,3101.81 6728.61,3101.81 ; 5600,3362.95 6728.61,3362.95 ; 5801.33,3014.76 5801.33,3450 ; 5992.26,3014.76 5992.26,3450 ; 6335.48,3014.76 6335.48,3450 ; 6489.98,3014.76 6489.98,3450 ; 5600,3014.76 6728.61,3014.76 6728.61,3450 5600,3450 5600,3014.76
  text "Symbol" at 5652.23,3389.07 h36
  text "Quantity" at 5827.44,3389.07 h36
  text "Finished Hole Size" at 6018.38,3389.07 h36
  text "Plated" at 6361.59,3389.07 h36
  text "Hole Type" at 6516.1,3389.07 h36
  text "5" at 5827.44,3302.02 h30
  text "16.00mil (0.406mm)" at 6018.38,3302.02 h30
  text "PTH" at 6361.59,3302.02 h30
  text "Round" at 6516.1,3302.02 h30
  text "12" at 5827.44,3214.97 h30
  text "50.00mil (1.270mm)" at 6018.38,3214.97 h30
  text "PTH" at 6361.59,3214.97 h30
  text "Round" at 6516.1,3214.97 h30
  text "4" at 5827.44,3127.92 h30
  text "125.98mil (3.200mm)" at 6018.38,3127.92 h30
  text "PTH" at 6361.59,3127.92 h30
  text "Round" at 6516.1,3127.92 h30
  text "21 Total" at 5827.44,3040.87 h30
  text ".Layer_Name" at 577,-858.49 h30

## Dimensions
0,-400 to 1000,-400 on M2 Board Dimensions
0,0 to 0,2000 on M2 Board Dimensions
0,0 to 2400,0 on M2 Board Dimensions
